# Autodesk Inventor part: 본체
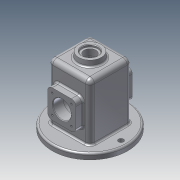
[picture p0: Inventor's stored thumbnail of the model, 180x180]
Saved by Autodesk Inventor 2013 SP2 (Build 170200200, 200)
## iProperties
Created: 2021-08
Part Number: 본체
Material: 알루미늄 6061
Document SubType Name: Modeling
Designer: kum60
Density: 2.71 g/cm^3
Mass: 826.051 g
Surface Area: 950.592 cm^2
Volume: 304.816 cm^3
Author: kum60
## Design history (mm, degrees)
sketch "스케치1"
  geometry: L1 (37, 37)-(-37, 37); L2 (-37, 37)-(-37, -37); L3 (-37, -37)-(37, -37); L4 (37, -37)-(37, 37); L5 (37, 37)-(-37, -37); L6 (-37, 37)-(37, -37); 1 further point
  constraints: 12 end point, 2 midpoint, 2 parallel, 1 horizontal, 1 perpendicular
  dimensions: "d0" = 74 distance of L3.end L2.end; "d1" = 74 distance of L2.end L1.end
extrude "돌출1" new body sketch "스케치1" stored distance "d2" = 100; taper "d3" = 0 deg
feature "쉘1" dims "d4" = 5
sketch "스케치2"
  geometry: L1 (74, -100)-(0, -100) reference; L2 (37, -50)-(37, -55); C1 r 16 at (37, -55); 1 further point
  constraints: 2 coincident, 2 end point, 1 centre point, 1 perpendicular
  dimensions: "d91" = 5 distance of L2.start L2.end; "d92" = 32 diameter of C1
extrude "돌출2" cut sketch "스케치2" stored distance "d6" = 0; taper "d7" = 0 deg
sketch "스케치15"
  geometry: L1 (12, -80)-(62, -80); L2 (62, -80)-(62, -30); L3 (62, -30)-(12, -30); L4 (12, -30)-(12, -80); L5 (12, -80)-(62, -30); L6 (62, -80)-(12, -30); C1 r 16 at (37, -55) reference; 1 further point
  constraints: 12 end point, 2 midpoint, 2 parallel, 1 horizontal, 1 perpendicular
  dimensions: "d93" = 50 distance of L3.end L2.end; "d94" = 50 distance of L2.end L1.end
extrude "돌출9" join sketch "스케치15" distance "d95" = 13; taper "d96" = 0 deg
sketch "스케치16"
  geometry: C1 r 16 at (32, 45) reference; C2 r 25 at (32, 45); 1 further point
  constraints: 1 centre point, 1 coincident
  dimensions: "d97" = 50 diameter of C2
extrude "돌출10" join sketch "스케치16" distance "d98" = 7; taper "d99" = -10 deg
sketch "스케치17"
  geometry: L1 (20, -72)-(54, -72); L2 (54, -72)-(54, -38); L3 (54, -38)-(20, -38); L4 (20, -38)-(20, -72); L5 (20, -72)-(54, -38); L6 (54, -72)-(20, -38); C1 r 16 at (37, -55) reference; 5 further points
  constraints: 12 end point, 3 coincident, 2 midpoint, 2 parallel, 1 horizontal, 1 perpendicular, 1 point on line
  dimensions: "d100" = 34 distance of L3.end L2.end; "d101" = 34 distance of L2.end L1.end
hole "구멍5" sketch "스케치17" at (20, -38), (54, -38), (54, -72), (20, -72) diameter "d102" = 3.242; stored, may be unused: countersink angle "d106" = 90 deg, drill point angle "d108" = 118 deg; dims "d103" = 8, "d104" = 28, "d105" = 4, "d107" = 10
sketch "스케치6"
  geometry: C1 r 25 at (0, 0); 1 further point
  constraints: 1 centre point, 1 coincident
  dimensions: "d34" = 50 diameter of C1
extrude "돌출5" join sketch "스케치6" distance "d35" = 10; taper "d36" = -6 deg
sketch "스케치13"
  geometry: C1 r 23.949 at (0, 0) reference; C2 r 20 at (0, 0); C3 r 30 at (0, 0)
  constraints: 2 centre point, 2 coincident
  dimensions: "d79" = 40 diameter of C2; "d80" = 60 diameter of C3
extrude "돌출8" cut sketch "스케치13" distance "d81" = 10; taper "d82" = -6 deg
sketch "스케치7"
  geometry: C1 r 23.949 at (0, 0) reference; 1 further point
  constraints: 1 coincident
hole "구멍2" sketch "스케치7" at (0, 0) diameter "d37" = 21; stored, may be unused: countersink angle "d41" = 90 deg, drill point angle "d43" = 118 deg; dims "d38" = 8, "d39" = 28, "d40" = 4, "d42" = 10
sketch "스케치10"
  geometry: L1 (32, 32)-(32, -32) reference; L2 (32, -32)-(-32, -32) reference; L3 (-32, -32)-(-32, 32) reference; L4 (-32, 32)-(32, 32) reference; C1 r 67 at (0, 0); 1 further point
  constraints: 1 centre point, 1 coincident
  dimensions: "d60" = 134 diameter of C1
extrude "돌출7" join sketch "스케치10" distance "d61" = 10; taper "d62" = 0 deg
fillet "모깎기7" dims "d63" = 3
fillet "모깎기8" dims "d64" = 3
fillet "모깎기5" dims "d58" = 8
sketch "스케치11"
  geometry: L1 (37, 29)-(37, -29) reference; L2 (55, 0)-(-55, 0); C1 r 64 at (0, 0) reference; 3 further points
  constraints: 3 coincident, 2 end point, 1 midpoint, 1 perpendicular
  dimensions: "d65" = 110 distance of L2.start L2.end
hole "구멍4" sketch "스케치11" at (55, 0), (-55, 0) diameter "d66" = 9; stored, may be unused: countersink angle "d70" = 90 deg, drill point angle "d72" = 118 deg; dims "d67" = 8, "d68" = 28, "d69" = 4, "d71" = 10
fillet "모깎기9" dims "d73" = 3
chamfer "모따기3" distance "d44" = 1; stored, may be unused: second distance "d45" = 2, angle "d46" = 45 deg
fillet "모깎기10" dims "d83" = 3
fillet "모깎기11" dims "d84" = 8
sketch "스케치14"
  geometry: L1 (49, 107)-(9, 107) reference; L2 (-8, 89)-(-8, 0) reference; 2 further points
  constraints: 1 other
  dimensions: "d85" = 28 distance from line of point (29, 79) L1; "d86" = 37 distance from line of point (29, 79) L2
feature "엠보싱2" sketch "스케치14" dims "d0" = 74, "d1" = 74, "d87" = 0.5, "d88" = 0
fillet "모깎기12" dims "d109" = 8
fillet "모깎기13" dims "d110" = 3
chamfer "모따기4" distance "d111" = 1; stored, may be unused: second distance "d112" = 2, angle "d113" = 45 deg
node "솔리드1"
mirror "대칭2"
